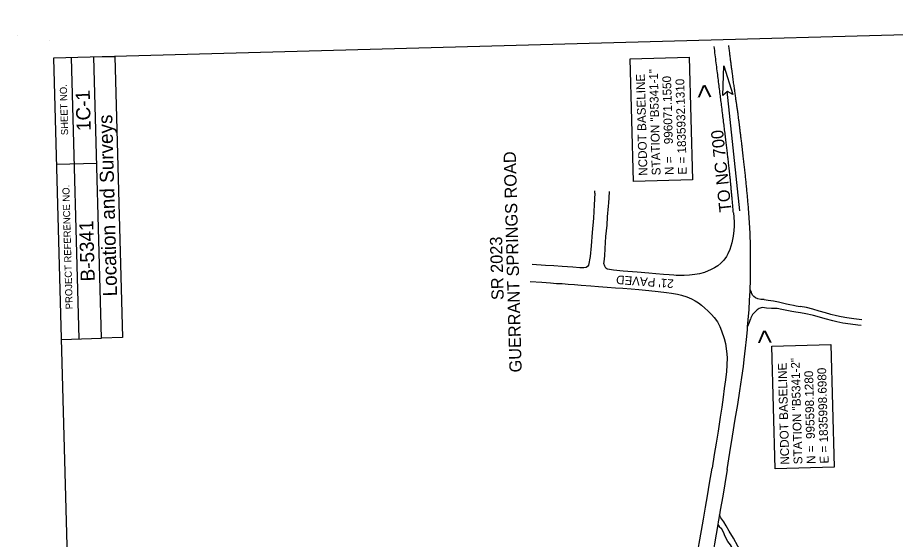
# Model space of a CAD drawing. Extents: x 1835096 to 1837089, y 993071 to 995976.
# Drawn here: x 1835096 to 1836175, y 995335 to 995976 of the extents above; entities that cross this region are included whole.
import ezdxf

# ---------------------------------------------------------------- set-up
doc = ezdxf.new("R2010")
doc.units = 0
for name, color, linetype in [('CTL Sheet Border CELL', 7, 'Continuous'), ('Default', 7, 'Continuous'), ('Exist Roads EOP', 7, 'Continuous'), ('Exist Roads EOP Cogo Point CELL', 7, 'Continuous'), ('Exist Roads EOP Other', 7, 'Continuous'), ('Exist Roads EOP Text', 7, 'Continuous'), ('Exist Roads Soil', 7, 'Continuous'), ('Old_Level_57', 7, 'Continuous'), ('Prop Terminator CELL', 7, 'Continuous'), ('Proposed Right of Way Monument PSD Text', 7, 'Continuous'), ('Sheet Data Field CELL', 7, 'Continuous')]:
    doc.layers.add(name, color=color, linetype=linetype)

msp = doc.modelspace()

# ---------------------------------------------------------------- linework, layer by layer
at = {"layer": 'CTL Sheet Border CELL'}
msp.add_lwpolyline([(1835140.8, 995926.5), (1835212, 993318.7), (1837037.4, 993368.6), (1836966.2, 995976.3)], close=True, dxfattribs=at)
at = {"layer": 'Default'}
msp.add_line((1835984.1, 995738.8), (1835968.5, 995885.8), dxfattribs=at)
for points in [[(1835853.2, 995774.7), (1835849.1, 995925.6), (1835921.6, 995927.6), (1835925.7, 995776.7)], [(1836027.4, 995421.3), (1836023.3, 995572.2), (1836095.9, 995574.1), (1836100, 995423.3)]]:
    msp.add_lwpolyline(points, close=True, dxfattribs=at)
at = {"layer": 'Exist Roads EOP'}
for points in [[(1835996.5, 995711.3), (1835995.9, 995724), (1835995.1, 995736)], [(1835976.8, 995719.6), (1835976.5, 995714.6), (1835975.7, 995707.5), (1835974, 995699.4), (1835971.8, 995691.2), (1835969.3, 995685.7), (1835967.9, 995683.3)], [(1835996.6, 995641.4), (1835997, 995653.4), (1835997.2, 995667.6), (1835997.2, 995682.8), (1835997, 995695.3), (1835996.5, 995711.3)], [(1835967.9, 995683.3), (1835967.5, 995682.5), (1835964.4, 995678.1), (1835960.8, 995674.4), (1835956.8, 995671), (1835952.7, 995668.5), (1835948.1, 995666.1), (1835945.2, 995664.7), (1835940.4, 995662.9), (1835934.6, 995661.3), (1835928.8, 995660.3), (1835922.3, 995659.6), (1835915.6, 995659.1), (1835905.7, 995658.9), (1835903, 995659.7), (1835897.3, 995660), (1835890.3, 995660.5), (1835880.7, 995661.2), (1835872.2, 995661.9)], [(1835792.1, 995668.5), (1835787.4, 995668.6), (1835778.9, 995669.2), (1835765.7, 995670.1), (1835755.6, 995670.8), (1835745, 995671.5), (1835729, 995672.7)], [(1835872.2, 995661.9), (1835858, 995663.2), (1835840.5, 995664.5), (1835828.8, 995665.7), (1835824, 995666.3)], [(1835726.4, 995651.8), (1835740.8, 995650.8), (1835751.3, 995649.9), (1835758.7, 995649.3), (1835765.5, 995649.1), (1835773.1, 995648.5), (1835780.8, 995647.9), (1835789.1, 995647.3), (1835800.7, 995646.2), (1835810.3, 995645.5), (1835820.9, 995644.7), (1835831.1, 995643.9), (1835840.3, 995643.4), (1835850.6, 995642.6), (1835859.9, 995641.9), (1835872.3, 995640.8), (1835883.6, 995639.6), (1835893.8, 995638.2), (1835900.1, 995637.5), (1835907.3, 995636.2), (1835912.3, 995634.9), (1835918.7, 995632.8), (1835924.7, 995630.2), (1835929.1, 995627.9), (1835933, 995625.5), (1835936.9, 995622.5), (1835940.8, 995619.1), (1835944.5, 995615.5), (1835949, 995611), (1835952.4, 995607.4)], [(1835993.4, 995595.9), (1835994.2, 995604.5), (1835995.3, 995617.1), (1835996, 995628.3), (1835996.5, 995640.1), (1835996.6, 995641.4)], [(1835952.4, 995607.4), (1835956.4, 995602.2), (1835959.5, 995596.5), (1835961.4, 995590.9), (1835964.6, 995581.8), (1835966.4, 995575.5)], [(1835968.4, 995420.7), (1835971.7, 995441.4), (1835975, 995461.5), (1835978.4, 995482.3), (1835981.4, 995500.6), (1835984, 995517.4), (1835986.4, 995533.5), (1835988.3, 995547.2), (1835989.3, 995555.9), (1835990.9, 995569.8), (1835992, 995580.2), (1835993.2, 995592.4), (1835993.4, 995595.9)], [(1835966.4, 995575.5), (1835967.6, 995566.2), (1835968.2, 995558.3), (1835967.9, 995548.8), (1835967.5, 995541.2), (1835966.3, 995530.7), (1835964.8, 995520.2), (1835963.4, 995509.3), (1835961.7, 995497.1), (1835959.9, 995485), (1835957.2, 995467.5), (1835954.8, 995453), (1835952.6, 995438.9), (1835949.8, 995422.1)], [(1835922.9, 995263.6), (1835925.4, 995279), (1835927.7, 995292.7), (1835929.9, 995305.7), (1835932.4, 995319.6), (1835934, 995329.4), (1835937, 995345.7), (1835939.3, 995359.3), (1835941.9, 995374.3), (1835944.3, 995388.1), (1835946.8, 995403.6), (1835949.8, 995422.1)], [(1835968.4, 995420.7), (1835965.4, 995402.8), (1835962.9, 995387.7), (1835959.9, 995370.5), (1835958.9, 995364.6)], [(1835958.9, 995364.6), (1835957.4, 995356.1), (1835956.9, 995353.1)], [(1835956.9, 995353.1), (1835954.9, 995341.2), (1835952.9, 995329.1), (1835950.5, 995314.5), (1835947.2, 995296.1), (1835944.9, 995282.9), (1835941.7, 995264.4)]]:
    msp.add_lwpolyline(points, dxfattribs=at)
for points in [[(1835976.1, 995736.3), (1835972.3, 995778.8), (1835967.7, 995818.7), (1835959.2, 995887.2), (1835952.4, 995940.8)], [(1835986.4, 995820.8), (1835982.7, 995851.8), (1835978.7, 995879.2), (1835974.3, 995910.8), (1835970.4, 995942.1)], [(1835995.1, 995736), (1835992.9, 995762.1), (1835989.6, 995794.3), (1835986.4, 995820.8)]]:
    msp.add_open_spline(points, degree=2, dxfattribs=at)
at = {"layer": 'Exist Roads EOP Cogo Point CELL'}
msp.add_lwpolyline([(1835976.1, 995736.3), (1835976.8, 995725), (1835976.8, 995719.6)], dxfattribs=at)
at = {"layer": 'Exist Roads EOP Other'}
for points in [[(1835805.8, 995760.4), (1835805.9, 995763.3)], [(1835820.4, 995667.3), (1835819.5, 995668.3), (1835818, 995670.7), (1835817, 995673.7), (1835817.1, 995676), (1835817.9, 995683.2), (1835818.3, 995692.1), (1835819.4, 995707.1), (1835820.8, 995720.8), (1835821.5, 995731.3), (1835822.7, 995744.5), (1835823, 995748.6), (1835823.5, 995754.4), (1835824, 995762.3)], [(1835805.8, 995760.4), (1835805, 995746.1), (1835804.1, 995729.8), (1835802.6, 995711.8), (1835801.4, 995695.5), (1835799.9, 995682.4), (1835798, 995671.9), (1835796.7, 995670.1), (1835795.3, 995669), (1835792.1, 995668.5)], [(1835824, 995666.3), (1835823.9, 995666.3), (1835821.4, 995667), (1835820.4, 995667.3)]]:
    msp.add_lwpolyline(points, dxfattribs=at)
at = {"layer": 'Exist Roads Soil'}
for points in [[(1835996.6, 995641.4), (1835998, 995638.6)], [(1836014, 995629.5), (1836009.8, 995629.7), (1836006, 995630.4), (1836003.1, 995631.8), (1836001.1, 995633.2), (1835999.5, 995635.1), (1835998, 995638.6)], [(1836014, 995629.5), (1836018.6, 995628.9), (1836025.4, 995627.8), (1836031.5, 995626.7), (1836036.2, 995625.5), (1836041.3, 995624.4), (1836045.4, 995623.5), (1836049.7, 995622.7), (1836053.3, 995622), (1836058.1, 995621)], [(1836072.9, 995610.3), (1836065.2, 995612), (1836058.4, 995613.3), (1836052.7, 995614.1), (1836047.7, 995614.9), (1836041.8, 995615.9), (1836035.4, 995617.4), (1836029.7, 995618.5), (1836022.8, 995618.7), (1836016.8, 995619.1), (1836012, 995619.7), (1836010.1, 995619.3), (1836007.6, 995618.4), (1836005.1, 995616.8), (1836003.2, 995614.9), (1836001.6, 995613.3), (1835999.7, 995611), (1835998.6, 995609.3), (1835997.5, 995607), (1835996.9, 995605.3)], [(1836133.7, 995604.7), (1836124, 995605.9), (1836115.6, 995606.9), (1836108.6, 995608.1), (1836102.7, 995609.3), (1836095.9, 995611.1), (1836089.2, 995613.1), (1836081.6, 995615.4), (1836073.6, 995617.6), (1836066, 995619.7), (1836058.1, 995621)], [(1835993.4, 995595.9), (1835995.7, 995601.8), (1835996.9, 995605.3)], [(1836098.3, 995603.3), (1836088.7, 995606), (1836081.7, 995608), (1836074.5, 995609.9), (1836072.9, 995610.3)], [(1836133, 995597.6), (1836129, 995598), (1836119.8, 995599.1), (1836110.4, 995600.6), (1836103.3, 995602), (1836098.3, 995603.3)], [(1835988.7, 995315.3), (1835981.7, 995326.1), (1835976.1, 995336), (1835970.8, 995344.9), (1835967, 995351.4), (1835964.3, 995356.1), (1835960.8, 995360.9), (1835959.6, 995362.8), (1835958.9, 995364.6)], [(1835956.9, 995353.1), (1835958.7, 995350.6), (1835961.5, 995348)], [(1835980.5, 995315.4), (1835975.4, 995323), (1835972.4, 995327.7), (1835969.4, 995332.2), (1835965.9, 995338.2), (1835963.8, 995343.4), (1835961.5, 995348)]]:
    msp.add_lwpolyline(points, dxfattribs=at)
at = {"layer": 'Prop Terminator CELL'}
msp.add_lwpolyline([(1835963, 995880.3), (1835964.3, 995916.8), (1835975.5, 995881.8), (1835968.6, 995885.5)], close=True, dxfattribs=at)
at = {"layer": 'Sheet Data Field CELL'}
for p, q in [((1835096.5, 995954.8), (1835096.5, 995954.8)), ((1835135.7, 995948.1), (1835135.7, 995948.1)), ((1835135.7, 995948.1), (1835135.7, 995948.1)), ((1835172, 995581.2), (1835162.6, 995927.1)), ((1835144.4, 995796.1), (1835193.9, 995797.4)), ((1835150.3, 995580.6), (1835199.8, 995582))]:
    msp.add_line(p, q, dxfattribs=at)
msp.add_lwpolyline([(1835199.8, 995582), (1835190.3, 995927.8), (1835215.9, 995928.5), (1835225.4, 995582.7)], close=True, dxfattribs=at)

# ---------------------------------------------------------------- texts
at = {"layer": 'Default'}
for s, rotation, p in [('TO NC 700', 96.0489, (1835973.9, 995737.9)), ('GUERRANT SPRINGS ROAD', 91.5643, (1835716, 995540.1)), ('SR 2023', 91.5643, (1835693.9, 995629.1))]:
    msp.add_text(s, height=15, rotation=rotation, dxfattribs=at).set_placement(p)
at = {"layer": 'Exist Roads EOP Text'}
msp.add_text("21' PAVED", height=10.65, rotation=175.7687, dxfattribs=at).set_placement((1835903, 995654.1))
at = {"layer": 'Old_Level_57'}
for p in [(1835951.7, 995877), (1836025.7, 995575.2)]:
    msp.add_text('>', height=23, rotation=91.5785, dxfattribs=at).set_placement(p)
at = {"layer": 'Proposed Right of Way Monument PSD Text'}
for s, height, p in [('NCDOT BASELINE', 10.752, (1835870.5, 995781.9)), ('STATION "B5341-1"', 10.752, (1835886.6, 995782.4)), ('996071.1550', 10.752, (1835901.7, 995820.7)), ('E = 1835932.1310', 10.752, (1835918.8, 995783.3)), ('N = ', 10.75, (1835902.7, 995782.8)), ('NCDOT BASELINE', 10.752, (1836044.8, 995426.6)), ('STATION "B5341-2"', 10.752, (1836060.9, 995427.1)), ('N =  995598.1280', 10.752, (1836077, 995427.5)), ('E = 1835998.6980', 10.752, (1836093.1, 995428))]:
    msp.add_text(s, height=height, rotation=91.5643, dxfattribs=at).set_placement(p)
at = {"layer": 'Sheet Data Field CELL'}
for s, height, p in [('SHEET NO.', 8.7, (1835158.7, 995831.8)), ('1C-1', 17.39, (1835186.5, 995837)), ('Location and Surveys', 17.392, (1835218.9, 995633.6)), ('PROJECT REFERENCE NO.', 8.696, (1835164.3, 995617.7)), ('B-5341', 17.39, (1835191.5, 995652))]:
    msp.add_text(s, height=height, rotation=91.5643, dxfattribs=at).set_placement(p)

doc.saveas('drawing.dxf')
